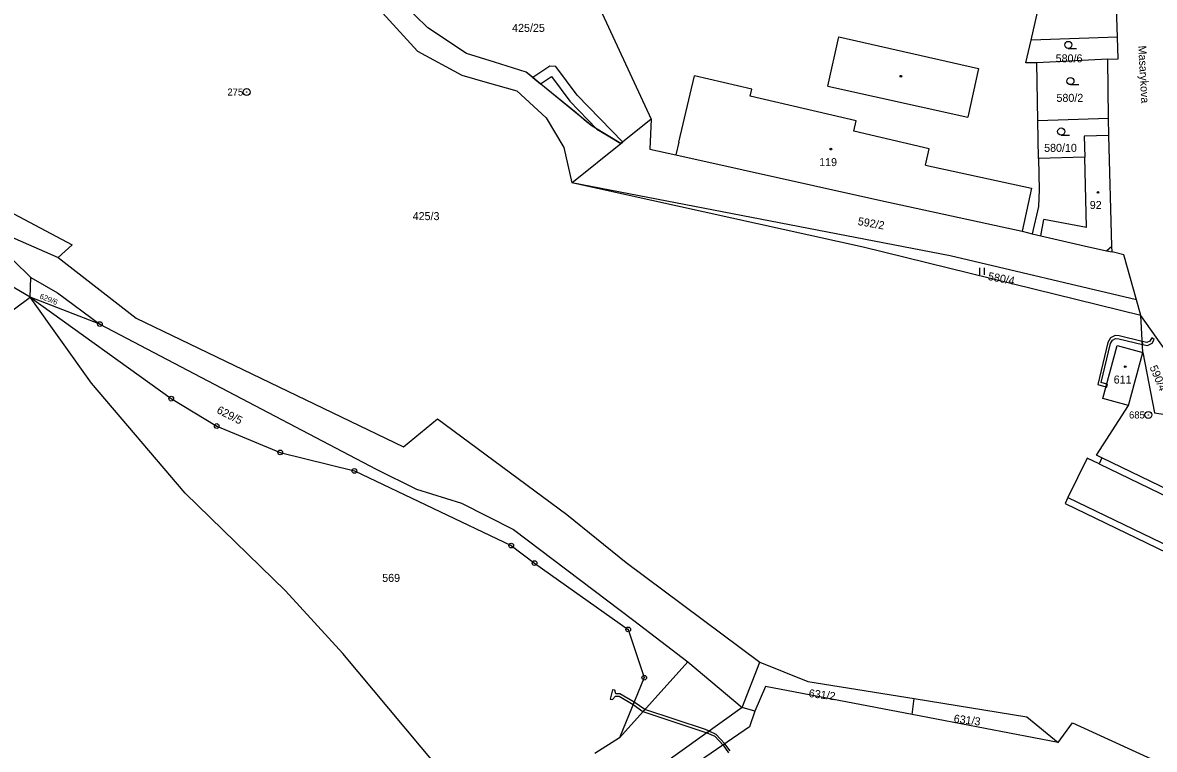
# Model space of a CAD drawing. Extents: x -758582 to -751794, y -998770 to -994350.
# Drawn here: x -756110.2 to -755869.9, y -995841.1 to -995686.7 of the extents above; entities that cross this region are included whole.
import ezdxf

# ---------------------------------------------------------------- set-up
doc = ezdxf.new("R2010")
doc.units = 0
for name, color, linetype in [('Hranice parcel', 7, 'Continuous'), ('Parcelní čísla', 7, 'Continuous'), ('Pop  PČ popisy', 7, 'Continuous'), ('Vnitřní kresba', 7, 'Continuous'), ('Věcná břemena k části', 7, 'Continuous'), ('Značky bodu BP', 7, 'Continuous'), ('Značky budov', 7, 'Continuous'), ('Značky kultur', 7, 'Continuous')]:
    doc.layers.add(name, color=color, linetype=linetype)

msp = doc.modelspace()

# ---------------------------------------------------------------- linework, layer by layer
at = {"layer": 'Hranice parcel'}
for p, q in [((-755877.74, -995689.77), (-755879.46, -995638.39)), ((-756024.2, -995687.83), (-756029.7, -995682.47)), ((-755988.07, -995682.82), (-755976.75, -995707.23)), ((-755877.74, -995689.77), (-755896.07, -995690.47)), ((-755879.8, -995694.49), (-755894.86, -995695.23)), ((-755879.63, -995707.02), (-755879.8, -995694.49)), ((-755894.63, -995707.51), (-755894.86, -995695.23)), ((-755894.63, -995707.51), (-755879.63, -995707.02)), ((-755879.58, -995710.66), (-755879.63, -995707.02)), ((-755976.75, -995707.23), (-755983.2, -995712.39)), ((-755894.48, -995715.58), (-755894.63, -995707.51)), ((-755993.63, -995720.73), (-755983.2, -995712.39)), ((-756108.62, -995745.03), (-756134.96, -995729.61)), ((-756108.62, -995745.03), (-756108.48, -995740.84)), ((-756140.98, -995769.1), (-756108.62, -995745.03)), ((-756093.8, -995750.74), (-756108.62, -995745.03)), ((-756108.62, -995745.03), (-756078.66, -995766.58)), ((-755872.8, -995748.95), (-755873.72, -995745.62)), ((-755872.35, -995756.76), (-755872.8, -995748.95)), ((-755877.8, -995755.28), (-755872.35, -995756.76)), ((-755875.41, -995768.05), (-755872.35, -995756.76)), ((-755882.19, -995778.61), (-755875.41, -995768.05)), ((-755881.1, -995779.14), (-755882.19, -995778.61)), ((-755825.41, -995806.11), (-755881.1, -995779.14)), ((-755968.96, -995822.45), (-755983.5, -995838.59)), ((-755968.96, -995822.45), (-755957.41, -995832.15)), ((-755957.41, -995832.15), (-755953.67, -995822.54)), ((-755978.22, -995825.84), (-755983.5, -995838.59)), ((-755921.32, -995833.66), (-755920.93, -995830.3)), ((-755954.75, -995832.96), (-755957.41, -995832.15)), ((-755890.34, -995839.6), (-755921.32, -995833.66)), ((-755983.5, -995838.59), (-755988.7, -995841.97))]:
    msp.add_line(p, q, dxfattribs=at)
for points in [[(-756294.02, -995651.36), (-756288.23, -995651.39), (-756234.04, -995677.25), (-756112.13, -995737.22), (-756108.48, -995740.84)], [(-756278.41, -995650.64), (-756249.66, -995666.5), (-756202.65, -995690.97), (-756163.1, -995710.12), (-756102.69, -995736.62)], [(-756278.41, -995650.64), (-756264.24, -995653.87), (-756172.36, -995695.34), (-756099.72, -995733.9), (-756102.69, -995736.62)], [(-755896.07, -995690.47), (-755893.79, -995680.36), (-755895.97, -995679.88)], [(-755989.31, -995708.68), (-756003.31, -995697.22), (-756010.01, -995695.13), (-756015.96, -995693.28), (-756024.2, -995687.83)], [(-755879.8, -995694.49), (-755877.59, -995694.41), (-755877.74, -995689.77)], [(-755894.86, -995695.23), (-755897.17, -995695.23), (-755896.07, -995690.47)], [(-755983.2, -995712.39), (-755985.85, -995710.78), (-755989.31, -995708.68)], [(-755976.75, -995707.23), (-755977.03, -995713.6), (-755971.55, -995714.81), (-755927.99, -995724.46), (-755897.98, -995731.03), (-755895.83, -995731.56)], [(-755879.58, -995710.66), (-755884.83, -995710.8), (-755884.71, -995715.28), (-755894.48, -995715.58)], [(-755878.9, -995735.4), (-755878.96, -995734.2), (-755879.58, -995710.66)], [(-755894.48, -995715.58), (-755894.36, -995722.22), (-755894.54, -995725.8), (-755895.83, -995731.56)], [(-755872.8, -995748.95), (-755931.77, -995734.38), (-755993.63, -995720.73)], [(-755873.72, -995745.62), (-755913.28, -995736.22), (-755993.63, -995720.73)], [(-755895.83, -995731.56), (-755894, -995731.99), (-755884.81, -995734.12), (-755880.07, -995735.15), (-755878.9, -995735.4)], [(-755873.72, -995745.62), (-755876.37, -995736.03), (-755878.9, -995735.4)], [(-756102.69, -995736.62), (-756086.1, -995749.47), (-756029.36, -995776.84), (-756022.09, -995770.89), (-755994.69, -995791.17), (-755982.08, -995801.37), (-755953.67, -995822.54)], [(-756108.48, -995740.84), (-756102.82, -995744.09), (-756093.8, -995750.74)], [(-756019.11, -995848.38), (-756042.22, -995820.69), (-756054.42, -995807.4), (-756075.71, -995786.64), (-756095.61, -995763.32), (-756108.62, -995745.03)], [(-755860.88, -995770.92), (-755866.3, -995758.15), (-755872.8, -995748.95)], [(-756093.8, -995750.74), (-756035.15, -995781.58), (-756026.6, -995785.78), (-756017.03, -995788.8), (-756005.96, -995794.34), (-755980.45, -995813.73), (-755968.96, -995822.45)], [(-755875.41, -995768.05), (-755880.87, -995766.56), (-755877.8, -995755.28)], [(-755872.35, -995756.76), (-755869.91, -995769.59), (-755860.88, -995770.92)], [(-756078.66, -995766.58), (-756069, -995772.39), (-756055.52, -995777.99), (-756039.75, -995781.93), (-756006.47, -995797.78), (-756001.52, -995801.52), (-755981.63, -995815.6), (-755978.22, -995825.84)], [(-755881.1, -995779.14), (-755881.65, -995780.44), (-755884.19, -995779.21), (-755888.26, -995787.6)], [(-755888.26, -995787.6), (-755888.87, -995788.85), (-755830.62, -995817.06)], [(-755953.67, -995822.54), (-755943.5, -995826.67), (-755920.93, -995830.3)], [(-755921.32, -995833.66), (-755952.51, -995827.72), (-755954.75, -995832.96)], [(-755920.93, -995830.3), (-755896.98, -995834.16), (-755890.34, -995839.6)], [(-755957.41, -995832.15), (-755978.63, -995847.4), (-756008.02, -995862.42), (-756030.26, -995877.93), (-756044.68, -995899.13), (-756052.22, -995911.9), (-756068.45, -995948.84), (-756068.67, -995953.08)], [(-755954.75, -995832.96), (-755955.85, -995836.29), (-755995.87, -995863.75), (-756012.13, -995871.42), (-756023.02, -995881.32), (-756035.99, -995895.37), (-756047.63, -995915.1), (-756068.67, -995953.08)], [(-755890.34, -995839.6), (-755887.3, -995835.46), (-755731.32, -995906.85), (-755733.82, -995912.03)]]:
    msp.add_lwpolyline(points, dxfattribs=at)
at = {"layer": 'Vnitřní kresba'}
for p, q in [((-755939.25, -995700.2), (-755936.91, -995689.72)), ((-755936.91, -995689.72), (-755907.23, -995696.44)), ((-755907.23, -995696.44), (-755909.54, -995706.82)), ((-755970.88, -995712.11), (-755967.58, -995698.02)), ((-755955.39, -995700.87), (-755967.58, -995698.02)), ((-755955.73, -995702.32), (-755955.39, -995700.87)), ((-755939.25, -995700.2), (-755909.54, -995706.82)), ((-755933.2, -995707.6), (-755955.73, -995702.32)), ((-755933.71, -995709.75), (-755933.2, -995707.6)), ((-755917.71, -995713.5), (-755933.71, -995709.75)), ((-755970.88, -995712.11), (-755971.55, -995714.81)), ((-755918.53, -995717.02), (-755917.71, -995713.5)), ((-755884.31, -995730.25), (-755884.71, -995715.28)), ((-755918.53, -995717.02), (-755896.03, -995721.86)), ((-755896.03, -995721.86), (-755897.98, -995731.03)), ((-755894, -995731.99), (-755893.35, -995728.55)), ((-755884.31, -995730.25), (-755893.35, -995728.55)), ((-755880.07, -995735.15), (-755878.96, -995734.2)), ((-755881.65, -995780.44), (-755863.65, -995789.15)), ((-755888.26, -995787.6), (-755830.03, -995815.75))]:
    msp.add_line(p, q, dxfattribs=at)
at = {"layer": 'Věcná břemena k části'}
for points in [[(-756012.09, -995699.27), (-756005.28, -995701.2), (-755999.06, -995706.91), (-755995.32, -995713.24), (-755993.63, -995720.73), (-755983.2, -995712.39), (-755985.85, -995710.78), (-755989.31, -995708.68), (-755990.45, -995707.75), (-755992.71, -995705.9), (-756000.55, -995699.48), (-756002.32, -995698.03), (-756003.31, -995697.22), (-756010.01, -995695.13), (-756015.96, -995693.28), (-756024.2, -995687.83), (-756029.7, -995682.47), (-756033.78, -995684.61), (-756026.37, -995692.79), (-756016.96, -995697.88)], [(-756000.25, -995699.72), (-755997.89, -995698.14), (-755994, -995703.42), (-755988.26, -995709.32), (-755985.85, -995710.78), (-755983.2, -995712.39), (-755982.79, -995712.07), (-755992.48, -995702.12), (-755996.97, -995696.01), (-755998.26, -995695.98), (-756001.87, -995698.4)], [(-755880.04, -995763.5), (-755881.23, -995763.18), (-755879.26, -995754.88), (-755878.81, -995754.13), (-755878.15, -995753.78), (-755877.49, -995753.84), (-755872.45, -995755.06), (-755872.48, -995754.43), (-755877.39, -995753.24), (-755878.27, -995753.16), (-755879.23, -995753.67), (-755879.82, -995754.64), (-755881.95, -995763.6), (-755880.19, -995764.08)], [(-755870.46, -995753.69), (-755870.85, -995754.36), (-755871.48, -995754.67), (-755872.48, -995754.43), (-755872.45, -995755.06), (-755871.4, -995755.31), (-755870.41, -995754.82), (-755869.94, -995753.99)], [(-755880.04, -995763.5), (-755880.19, -995764.08), (-755880.01, -995764.13), (-755879.85, -995763.55)], [(-755980.39, -995831.07), (-755983.41, -995829.25), (-755984.29, -995829.27), (-755984.5, -995828.53), (-755984.99, -995828.42), (-755985.43, -995830.38), (-755984.94, -995830.49), (-755984.35, -995829.77), (-755983.55, -995829.75), (-755980.58, -995831.54)], [(-755978.49, -995833.03), (-755978.12, -995832.62), (-755980.39, -995831.07), (-755980.58, -995831.54)], [(-755978.49, -995833.03), (-755964.9, -995837.53), (-755964.43, -995837.2), (-755965.23, -995836.84), (-755978.12, -995832.62)], [(-755961.5, -995840.17), (-755961.08, -995839.88), (-755962.94, -995837.88), (-755964.43, -995837.2), (-755964.9, -995837.53), (-755963.22, -995838.3)]]:
    msp.add_lwpolyline(points, close=True, dxfattribs=at)
msp.add_lwpolyline([(-755960, -995841.4), (-755961.08, -995839.88), (-755961.5, -995840.17), (-755960.32, -995841.8)], dxfattribs=at)
at = {"layer": 'Značky bodu BP'}
for centre, radius in [((-756062.63, -995701.46), 0.75), ((-756062.63, -995701.46), 0.03), ((-756093.8, -995750.74), 0.5), ((-756093.8, -995750.74), 0.0303), ((-756078.66, -995766.58), 0.5), ((-756078.66, -995766.58), 0.0303), ((-755871.19, -995770.04), 0.75), ((-756069, -995772.39), 0.5), ((-755871.19, -995770.04), 0.03), ((-756069, -995772.39), 0.0303), ((-756055.52, -995777.99), 0.5), ((-756055.52, -995777.99), 0.0303), ((-756039.75, -995781.93), 0.5), ((-756039.75, -995781.93), 0.0303), ((-756006.47, -995797.78), 0.5), ((-756006.47, -995797.78), 0.0303), ((-756001.52, -995801.52), 0.5), ((-756001.52, -995801.52), 0.0303), ((-755981.63, -995815.6), 0.5), ((-755981.63, -995815.6), 0.0303), ((-755978.22, -995825.84), 0.5), ((-755978.22, -995825.84), 0.0303)]:
    msp.add_circle(centre, radius, dxfattribs=at)
at = {"layer": 'Značky budov'}
for centre in [(-755923.74, -995698.1), (-755938.59, -995713.58), (-755881.89, -995722.78), (-755876.11, -995759.79)]:
    msp.add_circle(centre, 0.175, dxfattribs=at)
at = {"layer": 'Značky kultur'}
for p, q in [((-755888.18, -995692.19), (-755886.43, -995692.19)), ((-755887.73, -995699.89), (-755885.98, -995699.89)), ((-755889.7, -995710.59), (-755887.95, -995710.59)), ((-755906.98, -995740.29), (-755906.98, -995738.79)), ((-755905.98, -995740.29), (-755905.98, -995738.79))]:
    msp.add_line(p, q, dxfattribs=at)
for centre in [(-755888.18, -995691.44), (-755887.73, -995699.14), (-755889.7, -995709.84)]:
    msp.add_circle(centre, 0.75, dxfattribs=at)

# ---------------------------------------------------------------- texts
at = {"layer": 'Parcelní čísla'}
for s, p in [('425/25', (-756006.28, -995688.68)), ('580/6', (-755890.87, -995695.16)), ('580/2', (-755890.7, -995703.54)), ('580/10', (-755893.32, -995714.16)), ('119', (-755941.08, -995717.19)), ('92', (-755883.63, -995726.29)), ('425/3', (-756027.39, -995728.66)), ('611', (-755878.55, -995763.37)), ('569', (-756033.86, -995805.5))]:
    msp.add_text(s, height=1.7, dxfattribs=at).set_placement(p)
for s, height, rotation, p in [('592/2', 1.7, 350, (-755932.98, -995729.68)), ('580/4', 1.7, 349, (-755905.34, -995741.35)), ('629/6', 1.14, 338, (-756106.7, -995745.24)), ('590/4', 1.7, 293, (-755870.97, -995759.91)), ('629/5', 1.7, 333, (-756069.15, -995769.53)), ('631/2', 1.7, 353, (-755943.37, -995829.95)), ('631/3', 1.7, 353, (-755912.58, -995835.34))]:
    msp.add_text(s, height=height, rotation=rotation, dxfattribs=at).set_placement(p)
at = {"layer": 'Pop  PČ popisy'}
msp.add_text('Masarykova', height=1.7, rotation=273, dxfattribs=at).set_placement((-755873.33, -995691.64))
at = {"layer": 'Značky bodu BP'}
for s, p in [('275', (-756066.73, -995702.21)), ('685', (-755875.29, -995770.79))]:
    msp.add_text(s, height=1.5, dxfattribs=at).set_placement(p)

doc.saveas('drawing.dxf')
